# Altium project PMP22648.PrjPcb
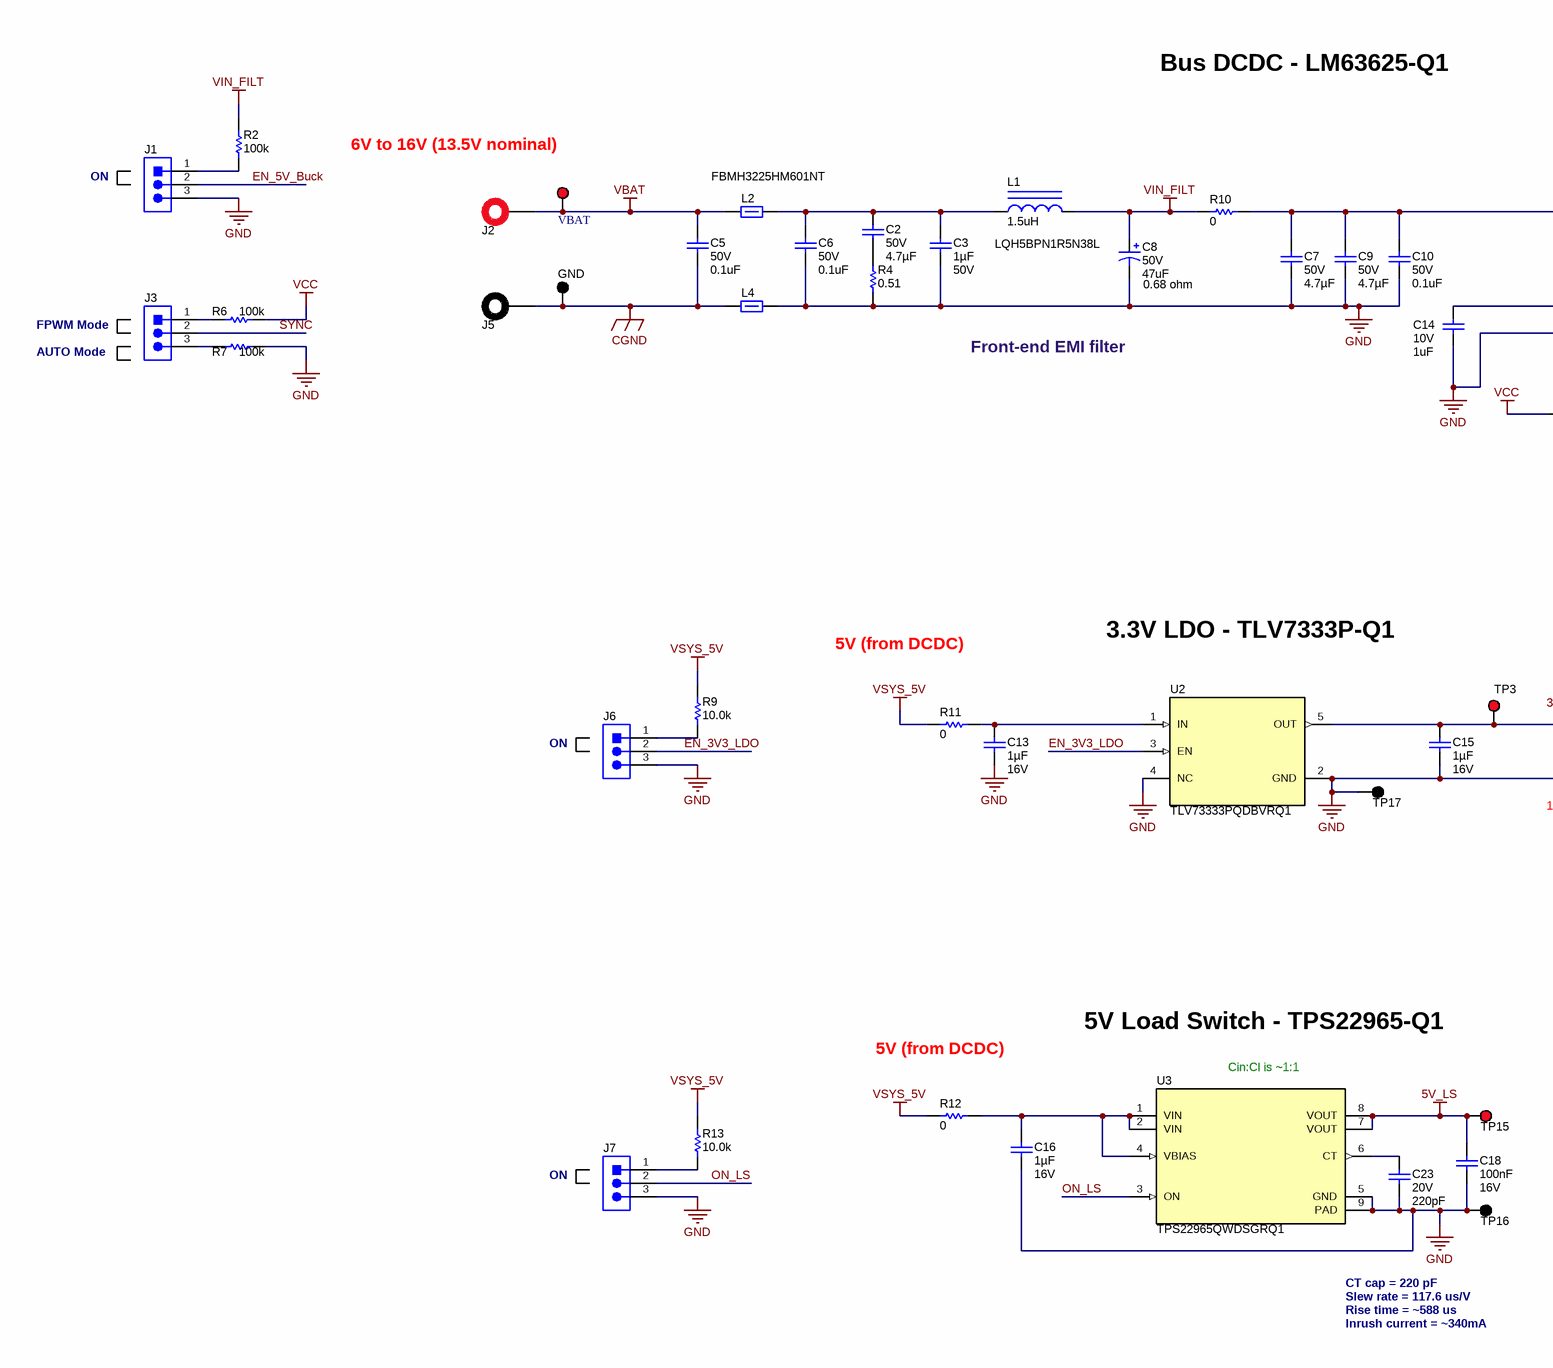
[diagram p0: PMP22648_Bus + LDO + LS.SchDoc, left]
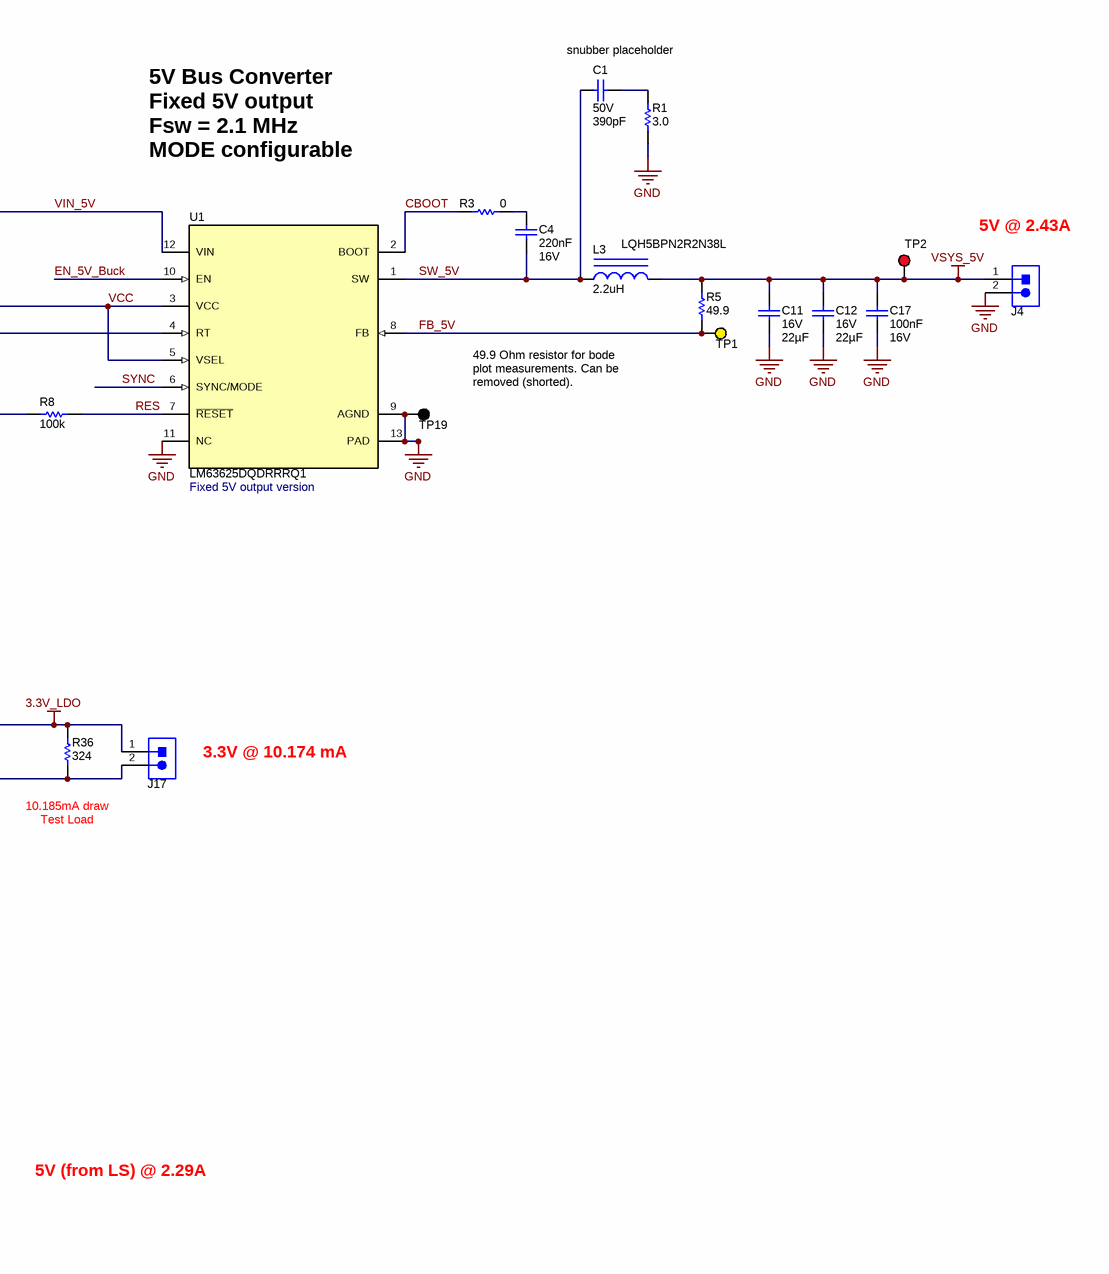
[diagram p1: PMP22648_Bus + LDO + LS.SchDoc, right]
CopyrightYear: 2020; PCB_Layout: Sahana Krishnan; PCB_Rev: E1; PRJ_Customer: Public Release; PRJ_Engineer: Sahana Krishnan; PRJ_Number: PMP22648; SCH_Rev: E1; TechSupport: http://www.ti.com/support; TID: N/A
2 sheets, 131 parts. Net scope: global (net labels, ports and power ports of the same name join across sheets).
Board file: PMP22648_PCB.PcbDoc
Sheets:
  PMP22648_Bus + LDO + LS.SchDoc
  PMP22648_PoL DCDC.SchDoc

## Sheet PMP22648_Bus + LDO + LS.SchDoc
size A2; Date: Not shown in title block; ApprovedBy: Not shown in title block; CheckedBy: Not shown in title block; Author: Not shown in title block; CompanyName: Not shown in title block; Engineer: Not shown in title block; Organization: Not shown in title block; Address1: Not shown in title block; Address2: Not shown in title block; Address3: Not shown in title block; Address4: Not shown in title block; DocumentNumber: 2; Revision: Use project parameter SCH_Rev; SheetNumber: 1; SheetTotal: 3; PageSetup: Record=PageOptions¦CenterHorizontal=True¦CenterVertical=True¦PrintScale=1.00¦XCorrection=1.00¦YCorrection=1.00¦PrintKind=0¦BorderSize=5000000¦LeftOffset=0¦BottomOffset=0¦Orientation=2¦PaperLength=1000¦PaperWidth=1000¦Scale=100¦PaperSource=15¦PrintQuality=600¦MediaType=1¦DitherType=10¦PaperKind=Letter¦PrintScaleMode=1

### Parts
C1  VDC_V: 50V  ValueDisplayed: 390pF  [0402S]  (hidden comment: GCM155R71H391KA37D)
C2  VDC_V: 50V  ValueDisplayed: 4.7µF  [1206_180]  (hidden comment: GCM31CC71H475KA03L)
C3  Cap_F: 1µF  VDC_V: 50V  [0805_HV]  (hidden comment: GCM21BR71H105KA03K)
C4  Cap_F: 220nF  VDC_V: 16V  [0603]  (hidden comment: GCM155R71C224KE02)
C5  VDC_V: 50V  ValueDisplayed: 0.1uF  [0402]  (hidden comment: GCM155R71H104KE02D)
C6  VDC_V: 50V  ValueDisplayed: 0.1uF  [0402]  (hidden comment: GCM155R71H104KE02D)
C7  VDC_V: 50V  ValueDisplayed: 4.7µF  [1206_180]  (hidden comment: GCM31CC71H475KA03L)
C8  Value1: 0.68 ohm  VDC_V: 50V  ValueDisplayed: 47uF  [Panasonic_D]  (hidden comment: EEEFT1H470AP)
C9  VDC_V: 50V  ValueDisplayed: 4.7µF  [1206_180]  (hidden comment: GCM31CC71H475KA03L)
C10  VDC_V: 50V  ValueDisplayed: 0.1uF  [0402]  (hidden comment: GCM155R71H104KE02D)
C11  VDC_V: 16V  ValueDisplayed: 22µF  [1210_270]  (hidden comment: CL32B226KOJVPNE)
C12  VDC_V: 16V  ValueDisplayed: 22µF  [1210_270]  (hidden comment: CL32B226KOJVPNE)
C13  Cap_F: 1µF  VDC_V: 16V  [0603]  (hidden comment: GCM188R71C105KA64J)
C14  VDC_V: 10V  ValueDisplayed: 1uF  [0402_070]  (hidden comment: GCM155C71A105KE38D)
C15  Cap_F: 1µF  VDC_V: 16V  [0603]  (hidden comment: GCM188R71C105KA64J)
C16  Cap_F: 1µF  VDC_V: 16V  [0603]  (hidden comment: GCM188R71C105KA64J)
C17  Cap_F: 100nF  VDC_V: 16V  [0603]  (hidden comment: GCM188R71C104KA37J)
C18  Cap_F: 100nF  VDC_V: 16V  [0603]  (hidden comment: GCM188R71C104KA37J)
C23  VDC_V: 20V  ValueDisplayed: 220pF  [0603]  (hidden comment: CGA3E2C0G1H221J080AA)
GND  5011  [Keystone5011]  (value not drawn)
J1  800-10-003-10-001000  [Mill-Max_800-10-003-10-001000]  (value not drawn)
J2  6091  [6091]  (value not drawn)
J3  800-10-003-10-001000  [Mill-Max_800-10-003-10-001000]  (value not drawn)
J4  PEC02SAAN  [CONN_PEC02SAAN]  (value not drawn)
J5  6092  [6092]  (value not drawn)
J6  800-10-003-10-001000  [Mill-Max_800-10-003-10-001000]  (value not drawn)
J7  800-10-003-10-001000  [Mill-Max_800-10-003-10-001000]  (value not drawn)
J17  PEC02SAAN  [CONN_PEC02SAAN]  (value not drawn)
L1  LQH5BPN1R5N38L  ValueDisplayed: 1.5uH  [LQH5BPN_38]
L2  FBMH3225HM601NT  [1210_280]
L3  LQH5BPN2R2N38L  ValueDisplayed: 2.2uH  [LQH5BPN_38]
L4  FBMH3225HM601NT  [1210_280]  (value not drawn)
R1  ValueDisplayed: 3.0  [0805]  (hidden comment: ERJ-6GEYJ3R0V)
R2  ValueDisplayed: 100k  [0402]  (hidden comment: RMCF0402FT100K)
R3  ValueDisplayed: 0  [0402S]  (hidden comment: CRCW04020000Z0EDHP)
R4  ValueDisplayed: 0.51  [0603]  (hidden comment: ERJ-3RQFR51V)
R5  ValueDisplayed: 49.9  [0402]  (hidden comment: ERJ-2RKF49R9X)
R6  ValueDisplayed: 100k  [0402]  (hidden comment: RMCF0402FT100K)
R7  ValueDisplayed: 100k  [0402]  (hidden comment: RMCF0402FT100K)
R8  ValueDisplayed: 100k  [0402]  (hidden comment: RMCF0402FT100K)
R9  ValueDisplayed: 10.0k  [0402]  (hidden comment: CRCW040210K0FKED)
R10  ValueDisplayed: 0  [1206]  (hidden comment: CRCW12060000Z0EAHP)
R11  ValueDisplayed: 0  [0402]  (hidden comment: CRCW04020000Z0EDHP)
R12  ValueDisplayed: 0  [1206]  (hidden comment: CRCW12060000Z0EAHP)
R13  ValueDisplayed: 10.0k  [0402]  (hidden comment: CRCW040210K0FKED)
R36  ValueDisplayed: 324  [0603]  (hidden comment: CRCW0603324RFKEA)
TP1  5014  [Keystone5014]  (value not drawn)
TP2  5010  [Keystone5010]  (value not drawn)
TP3  5010  [Keystone5010]  (value not drawn)
TP15  5010  [Keystone5010]  (value not drawn)
TP16  5011  [Keystone5011]  (value not drawn)
TP17  5011  [Keystone5011]  (value not drawn)
TP19  5011  [Keystone5011]  (value not drawn)
U1  LM63625DQDRRRQ1  [DRR0012E]
U2  TLV73333PQDBVRQ1  [DBV0005A_N]
U3  TPS22965QWDSGRQ1  [DSG0008B]
VBAT  5010  [Keystone5010]  (value not drawn)

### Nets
3.3V_LDO: C15.1 J17.1 R36.2 TP3.1 U2.5(OUT)
5V_LS: C18.1 TP15.1 U3.7(VOUT) U3.8(VOUT)
CGND: C5.2 GND.1 J5.1 L4.1
GND: C3.2 C6.2 C7.2 C8.2(-) C9.2 C10.2 C11.2 C12.2 C13.2 C14.2 C15.2 C16.2 C17.2 C18.2 C23.2 J1.3 J4.2 J6.3 J7.3 J17.2 L4.2 R1.1 R4.1 R7.1 R36.1 TP16.1 TP17.1 TP19.1 U1.4(RT) U1.9(AGND) U1.11(NC) U1.13(PAD) U2.2(GND) U2.4(NC) U3.5(GND) U3.9(PAD)
VBAT: C5.1 J2.1 L2.1 VBAT.1
VCC: C14.1 R6.1 R8.2 U1.3(VCC) U1.5(VSEL)
VIN_FILT: C8.1(+) L1.2 R2.2 R10.1
VSYS_5V: C11.1 C12.1 C17.1 J4.1 L3.2 R5.2 R9.1 R11.1 R12.1 R13.1 TP2.1
CBOOT: R3.2 U1.2(BOOT)
EN_3V3_LDO: J6.2 U2.3(EN)
EN_5V_Buck: J1.2 U1.10(EN)
FB_5V: R5.1 TP1.1 U1.8(FB)
ON_LS: J7.2 U3.3(ON)
RES: R8.1 U1.7(~{RESET})
SW_5V: C1.2 C4.2 L3.1 U1.1(SW)
SYNC: J3.2 U1.6(SYNC/MODE)
VIN_5V: C7.1 C9.1 C10.1 R10.2 U1.12(VIN)
NetC1_1: C1.1 R1.2
NetC2_1: C2.1 C3.1 C6.1 L1.1 L2.2
NetC2_2: C2.2 R4.2
NetC4_1: C4.1 R3.1
NetC13_1: C13.1 R11.2 U2.1(IN)
NetC16_1: C16.1 R12.2 U3.1(VIN) U3.2(VIN) U3.4(VBIAS)
NetC23_1: C23.1 U3.6(CT)
NetJ1_1: J1.1 R2.1
NetJ3_1: J3.1 R6.2
NetJ3_3: J3.3 R7.2
NetJ6_1: J6.1 R9.2
NetJ7_1: J7.1 R13.2

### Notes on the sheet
- Bus DCDC - LM63625-Q1
- snubber placeholder
- 6V to 16V (13.5V nominal)
- ON
- 5V Bus Converter
  Fixed 5V output
  Fsw = 2.1 MHz
  MODE configurable
- (near J4) 5V @ 2.43A
- FPWM Mode
- Front-end EMI filter
- AUTO Mode
- 49.9 Ohm resistor for bode plot measurements. Can be removed (shorted).
- (near U1) Fixed 5V output version
- 5V (from DCDC)
- 3.3V LDO - TLV7333P-Q1
- 3.3V @ 10.174 mA
- Test Load
- 10.185mA draw
- 5V Load Switch - TPS22965-Q1
- (near U3) Cin:Cl is
  :1
- 5V (from LS) @ 2.29A
- CT cap = 220 pF
- Slew rate = 117.6 us/V
- Rise time = ~588 us
- Inrush current = ~340mA

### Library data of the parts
C1 = CMP-0080703-2: CAP, CERM, 390 pF, 50 V,+/- 10%, X7R, AEC-Q200 Grade 1, 0402; Manufacturer: MuRata; Cap_Case: 0402; SizeX_mm: 1; SizeZ_mm: 0.6; SizeY_mm: 0.5; AEC Qualified: Y; Value: 390pF; Polarized: N; AEC Category: Q200; TaMax_C: 125°C; TaMin_C: -55°C; SizeAreaWB_mm2: 3; U/M: EA
C2 C7 C9 = CMP-0085643-1: CAP, CERM, 4.7 µF, 50 V,+/- 10%, X7S, AEC-Q200 Grade 1, 1206; Manufacturer: MuRata; SizeZ_mm: 1.8; Polarized: N; AEC Category: Q200; SizeY_mm: 1.6; SizeAreaWB_mm2: 10.92; SizeArea_mm2: 5.12; Value: 4.7uF; TaMin_C: -55°C; AEC Qualified: Y; SizeX_mm: 3.2; AEC Grade: 1; Cap_Case: 1206; U/M: EA; TaMax_C: 125°C
C3 = CMP-0086249-1: CAP, CERM, 1 µF, 50 V,+/- 10%, X7R, AEC-Q200 Grade 1, 0805; Manufacturer: MuRata; Value: 1uF; AEC Qualified: Y; AEC Category: Q200; U/M: EA; AEC Grade: 1; SizeArea_mm2: 2.5; SizeAreaWB_mm2: 6.75; SizeZ_mm: 1.45; SizeX_mm: 2; Cap_Case: 0805; TaMax_C: 125°C; Polarized: N; SizeY_mm: 1.25; TaMin_C: -55°C
C4 = CMP-0007125-4: CAP, CERM, 0.22 uF, 16 V, +/- 10%, X7R, AEC-Q200 Grade 1, 0603; Manufacturer: MuRata; TaMin_C: -55°C; Polarized: N; SizeAreaWB_mm2: 4.68; Value1: Unknown; U/M: EA; Value: 0.22uF; TaMax_C: 125°C; SizeZ_mm: 1; SizeX_mm: 1.6; SizeY_mm: 0.8; SizeArea_mm2: 1.28; AEC Qualified: Y; AEC Category: Q200
C5 C6 C10 = CMP-0006356-1: CAP, CERM, 0.1 uF, 50 V, +/- 10%, X7R, AEC-Q200 Grade 1, 0402; Manufacturer: MuRata; TaMin_C: -55°C; Polarized: N; SizeAreaWB_mm2: 3; Value1: Unknown; U/M: EA; Value: 0.1uF; TaMax_C: 125°C; SizeZ_mm: 0.6; SizeX_mm: 1; SizeY_mm: 0.5; AEC Qualified: Y; Cap_F: 100nF; AEC Category: Q200
C8 = CMP-0011204-2: CAP, AL, 47 uF, 50 V, +/- 20%, 0.68 ohm, AEC-Q200 Grade 2, SMD; Manufacturer: Panasonic; TaMin_C: -55°C; ESR_ohm: 0.68; Polarized: Y; SizeAreaWB_mm2: 73.96; U/M: EA; Value: 47uF; TaMax_C: 105°C; SizeZ_mm: 6.1; SizeX_mm: 6.6; Cap_Case: 6.3x5.8mm; SizeArea_mm2: 43.56; CompType: Capacitor; Cap_F: 47µF; IRMS_A: 195mA; AEC Grade: 2; AEC Category: Q200
C11 C12 = CMP-0083755-1: CAP, CERM, 22 µF, 16 V,+/- 10%, X7R, AEC-Q200 Grade 1, 1210; Manufacturer: Samsung Electro-Mechanics; SizeAreaWB_mm2: 14.7; SizeArea_mm2: 8; AEC Qualified: Y; AEC Category: Q200; Value: 22uF; TaMax_C: 125°C; SizeZ_mm: 2.7; AEC Grade: 1; Polarized: N; TaMin_C: -55°C; SizeY_mm: 2.5; U/M: EA; SizeX_mm: 3.2; Cap_Case: 1210
C13 C15 C16 = CMP-0079154-1: CAP, CERM, 1 µF, 16 V,+/- 10%, X7R, AEC-Q200 Grade 1, 0603; Manufacturer: MuRata; SizeAreaWB_mm2: 4.68; SizeArea_mm2: 1.28; AEC Qualified: Y; AEC Category: Q200; Value: 1uF; TaMax_C: 125°C; SizeZ_mm: 1; Polarized: N; TaMin_C: -55°C; SizeY_mm: 0.8; U/M: EA; SizeX_mm: 1.6
C14 = CMP-0006349-2: CAP, CERM, 1 uF, 10 V, +/- 10%, X7S, AEC-Q200 Grade 1, 0402; Manufacturer: MuRata; TaMin_C: -55°C; Polarized: N; SizeAreaWB_mm2: 3; Value1: Unknown; U/M: EA; Value: 1uF; TaMax_C: 125°C; SizeZ_mm: 0.7; SizeX_mm: 1; SizeY_mm: 0.5; Cap_Case: 0402; AEC Qualified: Y; Cap_F: 1µF; AEC Category: Q200
C17 C18 = CMP-0007135-2: CAP, CERM, 0.1 uF, 16 V, +/- 10%, X7R, AEC-Q200 Grade 1, 0603; Manufacturer: MuRata; TaMin_C: -55°C; Polarized: N; SizeAreaWB_mm2: 4.68; Value1: Unknown; U/M: EA; Value: 0.1uF; TaMax_C: 125°C; SizeZ_mm: 1; SizeX_mm: 1.6; SizeY_mm: 0.8; SizeArea_mm2: 1.28; AEC Qualified: Y; AEC Category: Q200
C23 = CMP-0007072-2: CAP, CERM, 220 pF, 20 V, +/- 5%, C0G/NP0, AEC-Q200 Grade 1, 0603; Manufacturer: TDK; TaMin_C: -55°C; Polarized: N; SizeAreaWB_mm2: 4.68; Value1: Unknown; U/M: EA; Value: 220pF; TaMax_C: 125°C; SizeZ_mm: 1; SizeX_mm: 1.6; SizeY_mm: 0.8; SizeArea_mm2: 1.28; AEC Qualified: Y; AEC Category: Q200
GND TP16 TP17 TP19 = CMP-0055148-1: Test Point, Multipurpose, Black, TH; Manufacturer: Keystone; CNHeader: FALSE; Green_Lifecycle: Active; Green_REACh: Passed; ContactFinish: Silver; CT: TRUE
J1 J3 J6 J7 = CMP-0055086-1: Header, 100mil, 3x1, TH; Manufacturer: Mill-Max; CNHeader: TRUE; Green_Lifecycle: Active; Green_REACh: Passed; CT: FALSE
J2 = CMP-0055167-2: Standard Banana Jack, Insulated, Red; Manufacturer: Keystone; CT: TRUE; Green_REACh: Passed; CNHeader: FALSE; Green_Lifecycle: Active
J4 J17 = CMP-0002337-1: Header, 100mil, 2x1, Tin, TH; Manufacturer: Sullins Connector Solutions; CNHeader: TRUE; Current_A: 3A; Green_Lifecycle: Not Set; Shrouded: N; Gender: Male; Green_REACh: Incomplete; Voltage_V: 1.8kV; Row_Count: 1; Pitch_mm: 2.54; CT: FALSE; Cert_UL: Y
J5 = CMP-0055168-2: Standard Banana Jack, Insulated, Black; Manufacturer: Keystone; CT: TRUE; Green_REACh: Passed; CNHeader: FALSE; Green_Lifecycle: Active
L1 = CMP-0058725-1: Inductor, Wirewound, Ferrite, 1.5 uH, 4.5 A, 0.0168 ohm, SMD; Manufacturer: MuRata; Isat: 6.5A @ 30% inductance drop; Irms: 4.5A @ 40C rise; SizeAreaWB_mm2: 34.81; DCR_ohm: 0.0168; Value: 1.5uH; Imax_A: 4.5A; SizeZ_mm: 4; SizeX_mm: 4.9; SizeArea_mm2: 24.01; Ind_H: 1.5µH; AEC Qualified: N; AEC Category: Q200
L2 L4 = CMP-0003374-1: Ferrite Bead, 600 ohm @ 100 MHz, 3 A, 1210; Manufacturer: Taiyo Yuden; ZTyp@100MHz_Ohm: 600; SizeAreaWB_mm2: 14.7; DCR_ohm: 0.042; Value1: 0.042 ohm; Value: 600 ohm; Imax_A: 3A; SizeZ_mm: 2.8; SizeX_mm: 3.2; SizeY_mm: 2.5; SizeArea_mm2: 8
L3 = CMP-0058726-1: Inductor, Wirewound, Ferrite, 2.2 uH, 4.3 A, 0.0192 ohm, SMD; Manufacturer: MuRata; Isat: 5A @ 30% inductance drop; Irms: 4.3A @ 40C rise; SizeAreaWB_mm2: 34.81; DCR_ohm: 0.0192; Value: 2.2uH; Imax_A: 4.3A; SizeZ_mm: 4; SizeX_mm: 4.9; SizeArea_mm2: 24.01; Ind_H: 2.2µH; AEC Qualified: N; AEC Category: Q200
R1 = CMP-0020720-3: RES, 3.0, 5%, 0.125 W, AEC-Q200 Grade 0, 0805; Manufacturer: Panasonic; Power_W: 125mW; TempCo: 600 ppm/C; Value_Code: 3R00; Value: 3.0; EIA_Code: E24; Res_ohm: 3; SizeX_mm: 2; SizeY_mm: 1.25; SizeZ_mm: 1.45; Value2: 0.125W; SizeArea_mm2: 2.5; AEC Qualified: Y; VDC_V: 150V; AEC Category: Q200; AEC Grade: 0; SizeAreaWB_mm2: 6.75
R2 R6-R8 = CMP-0026753-1: RES, 100 k, 1%, 0.063 W, AEC-Q200 Grade 0, 0402; Manufacturer: Stackpole Electronics Inc; Power_W: 63mW; TempCo: 100 ppm/C; U/M: EA; Value: 100k; EIA_Code: E96; SizeX_mm: 1; SizeY_mm: 0.5; SizeZ_mm: 0.6; Value2: 0.063W; AEC Qualified: Y; VDC_V: 50V; AEC Grade: 0; AEC Category: Q200
R3 R11 = CMP-0081856-1: RES, 0, 0%, 0.2 W, AEC-Q200 Grade 0, 0402; Manufacturer: Vishay-Dale; SizeAreaWB_mm2: 3; SizeArea_mm2: 0.5; AEC Qualified: Y; AEC Category: Q200; Value: 0; SizeZ_mm: 0.6; Power_W: 200mW; VDC_V: 50V; Value2: 0.2W; SizeX_mm: 1
R4 = CMP-0022717-2: RES, 0.51, 1%, 0.1 W, AEC-Q200 Grade 1, 0603; Manufacturer: Panasonic; Power_W: 100mW; TempCo: 300 ppm/C; Value_Code: R510; U/M: EA; Value: 0.51; EIA_Code: E96; SizeX_mm: 1.6; SizeY_mm: 0.8; SizeZ_mm: 1; Value2: 0.1W; SizeArea_mm2: 1.28; AEC Qualified: Y; AEC Category: Q200
R5 = CMP-0026703-1: RES, 49.9, 1%, 0.1 W, AEC-Q200 Grade 0, 0402; Manufacturer: Panasonic; Power_W: 100mW; TempCo: 100 ppm/C; Value_Code: 49R9; U/M: EA; Value: 49.9; EIA_Code: E96; SizeX_mm: 1; SizeY_mm: 0.5; SizeZ_mm: 0.6; Value2: 0.1W; AEC Qualified: Y; VDC_V: 50V; AEC Grade: 0; AEC Category: Q200
R9 R13 = CMP-0025958-3: RES, 10.0 k, 1%, 0.063 W, AEC-Q200 Grade 0, 0402; Manufacturer: Vishay-Dale; Power_W: 63mW; TempCo: 100 ppm/C; Value_Code: 10k0; Value: 10.0k; EIA_Code: E96; Res_ohm: 10k; SizeX_mm: 1; SizeY_mm: 0.5; SizeZ_mm: 0.6; Value2: 0.063W; AEC Qualified: Y; VDC_V: 50V; AEC Category: Q200; AEC Grade: 0
R10 R12 = CMP-0086176-1: RES, 0, 0.75 W, AEC-Q200 Grade 0, 1206; Manufacturer: Vishay-Dale; Value: 0; SizeY_mm: 1.6; SizeX_mm: 3.2; Tolerance_%: 0%; SizeArea_mm2: 5.12; EIA_Code: E96; SizeAreaWB_mm2: 10.92; Power_W: 750mW; AEC Qualified: Y; SizeZ_mm: 1.35; Value2: 0.75W; AEC Category: Q200; VDC_V: 200V
R36 = CMP-0022333-5: RES, 324, 1%, 0.1 W, AEC-Q200 Grade 0, 0603; Manufacturer: Vishay-Dale; Power_W: 100mW; TempCo: 100 ppm/C; Value_Code: 324R; Value: 324; EIA_Code: E96; SizeX_mm: 1.6; SizeY_mm: 0.8; SizeZ_mm: 1; Value2: 0.1W; SizeArea_mm2: 1.28; AEC Qualified: Y; VDC_V: 75V; AEC Category: Q200; AEC Grade: 0
TP1 = CMP-0055151-1: Test Point, Multipurpose, Yellow, TH; Manufacturer: Keystone; CNHeader: FALSE; Green_Lifecycle: Active; Green_REACh: Passed; ContactFinish: Silver; CT: TRUE
TP2 TP3 TP15 VBAT = CMP-0055147-1: Test Point, Multipurpose, Red, TH; Manufacturer: Keystone; CNHeader: FALSE; Green_Lifecycle: Active; Green_REACh: Passed; ContactFinish: Silver; CT: TRUE
U1 = CMP-0861031-1: 3.5-V to 36-V, 2.5-A, Automotive Step-down Voltage Converter, DRR0012E (WSON-12); Manufacturer: Texas Instruments; AEC Category: Q200; SizeArea_mm2: 9; SizeAreaWB_mm2: 16; CompType: IC; AEC Qualified: Y; SizeY_mm: 3; SizeZ_mm: 0.8
U2 = CMP-0860155-1: Automotive capacitor-free 300-mA LDO regulator with foldback current limit for portable devices, DBV0005A (SOT-23-5); Manufacturer: Texas Instruments; SizeAreaWB_mm2: 14.82; SizeArea_mm2: 8.12; SizeY_mm: 2.9; CompType: IC; SizeZ_mm: 1.45; SizeX_mm: 2.8; AEC Category: Q200; AEC Qualified: Y
U3 = CMP-0073677-2: 5.5V, 4A, 16mΩ Automotive Load Switch With Adjustable Rise Time and Optional Quick Output Discharge, DSG0008B (WSON-8); Alternate Manufacturer: Texas Instruments; Green_Lifecycle: Active; SizeAreaWB_mm2: 9.0; Green_REACh: Passed; U/M: EA; SizeZ_mm: 0.8; SizeX_mm: 2.0; SizeArea_mm2: 4.0; CompType: IC

## Sheet PMP22648_PoL DCDC.SchDoc
size A2; Date: Not shown in title block; ApprovedBy: Not shown in title block; CheckedBy: Not shown in title block; Author: Not shown in title block; CompanyName: Not shown in title block; Engineer: Not shown in title block; Organization: Not shown in title block; Address1: Not shown in title block; Address2: Not shown in title block; Address3: Not shown in title block; Address4: Not shown in title block; DocumentNumber: 2; Revision: Use project parameter SCH_Rev; SheetNumber: 2; SheetTotal: 3; PageSetup: Record=PageOptions¦CenterHorizontal=True¦CenterVertical=True¦PrintScale=1.00¦XCorrection=1.00¦YCorrection=1.00¦PrintKind=0¦BorderSize=5000000¦LeftOffset=0¦BottomOffset=0¦Orientation=2¦PaperLength=1000¦PaperWidth=1000¦Scale=100¦PaperSource=15¦PrintQuality=600¦MediaType=1¦DitherType=10¦PaperKind=Letter¦PrintScaleMode=1
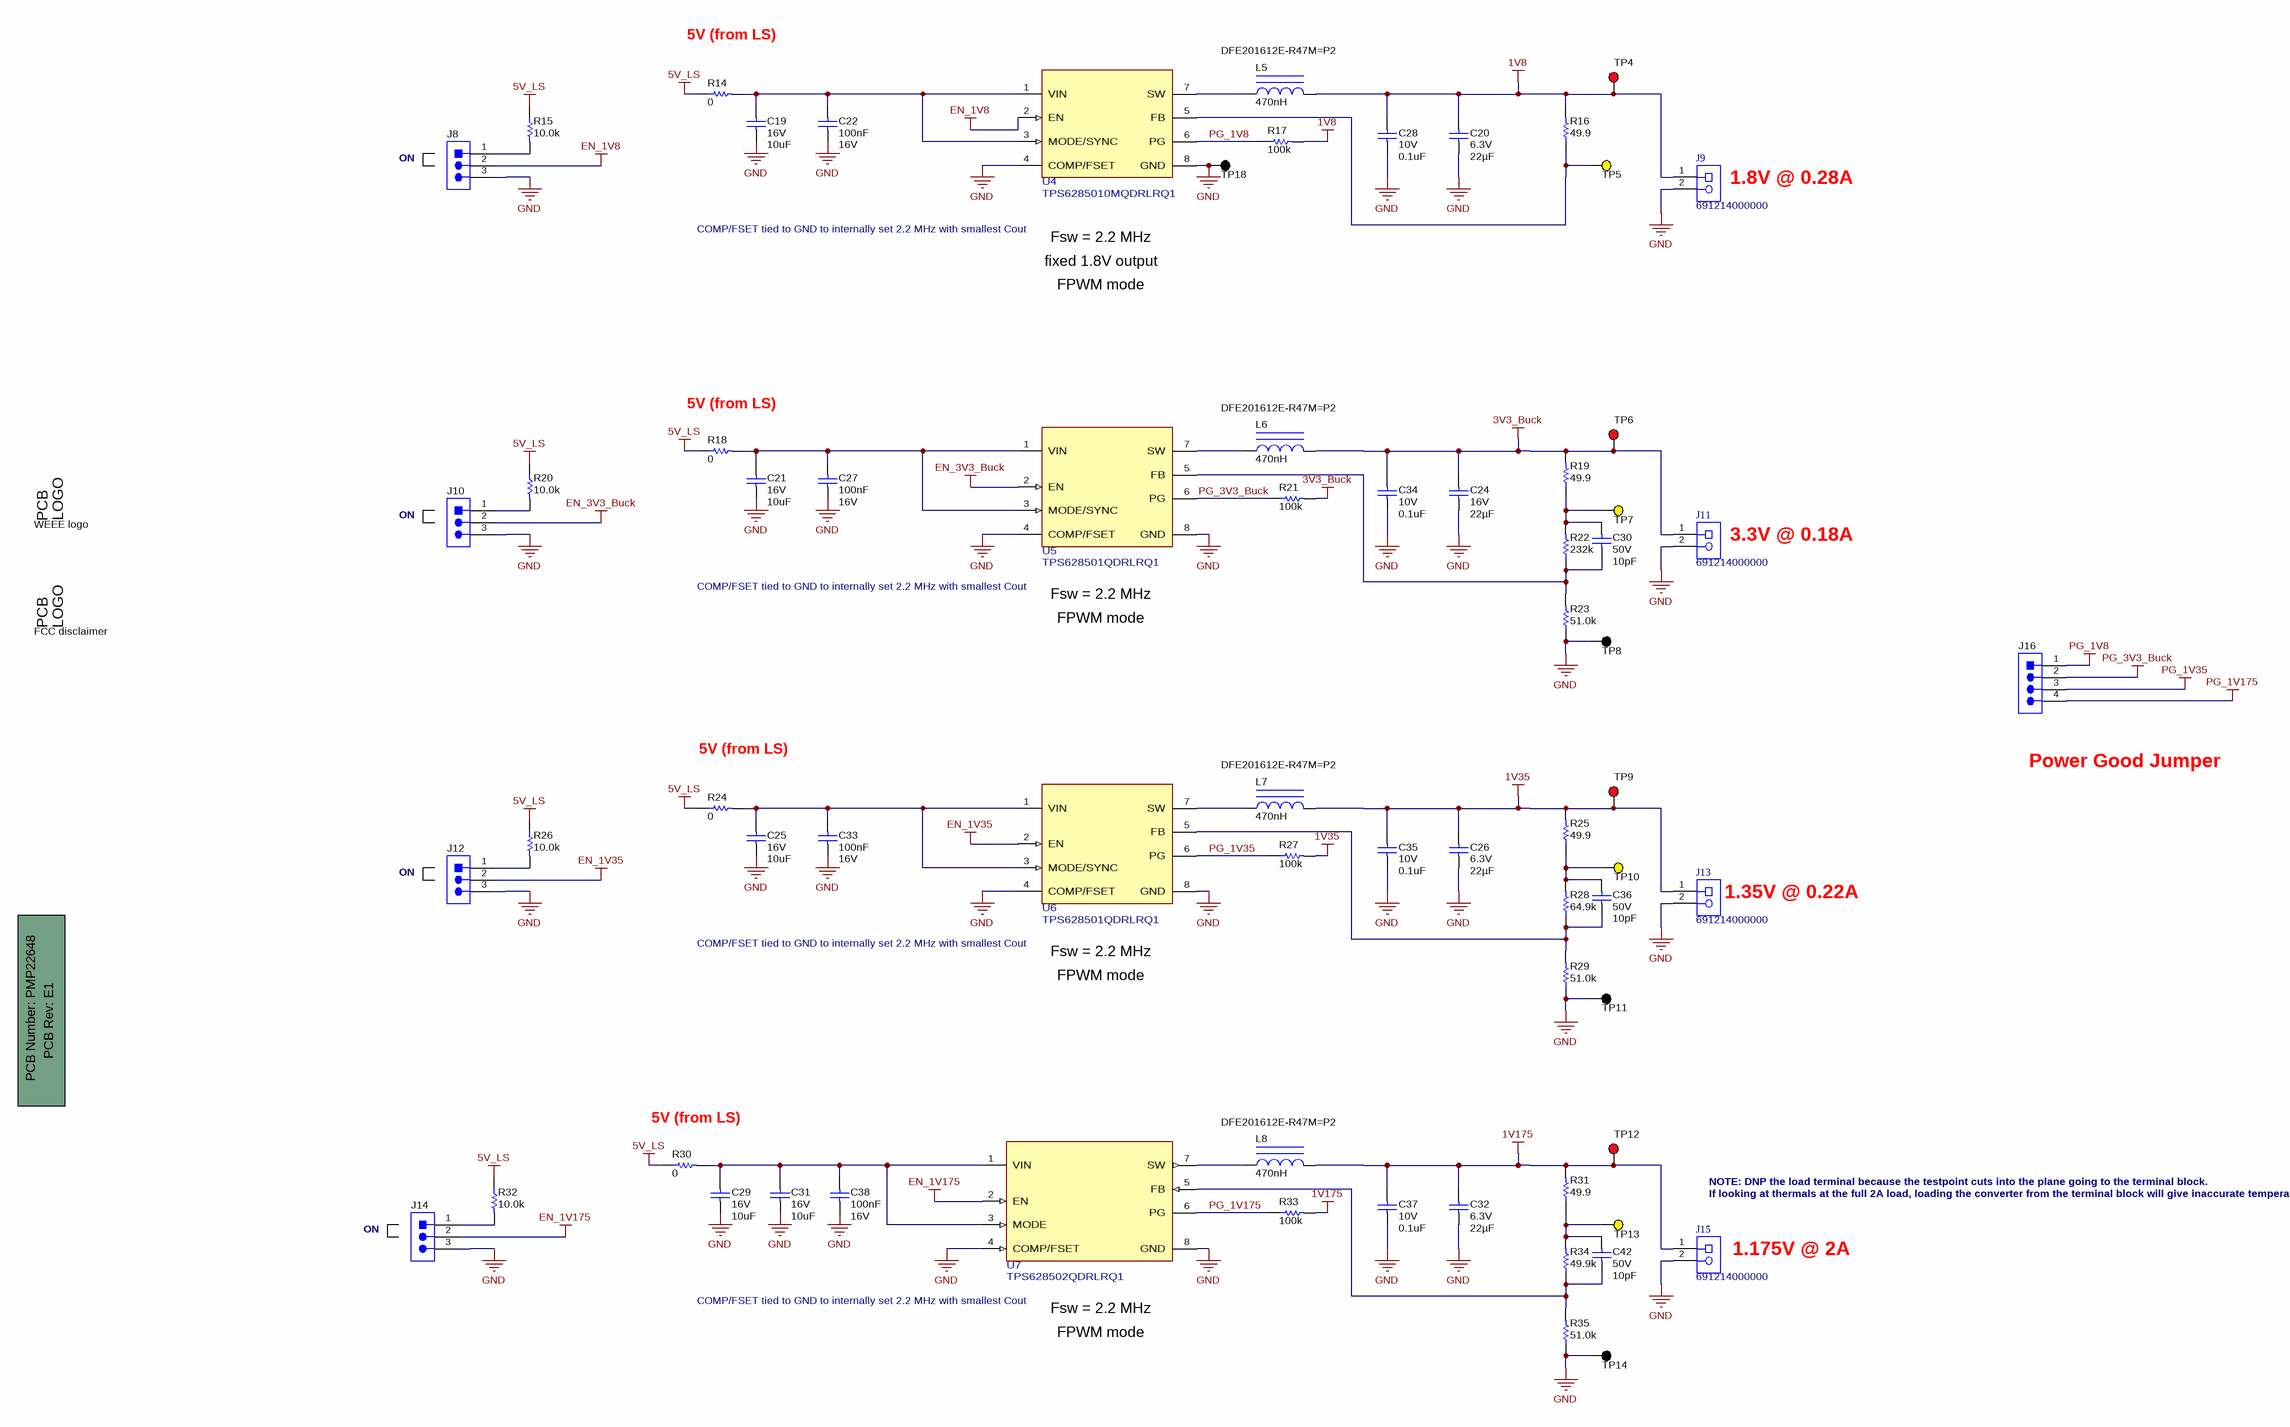
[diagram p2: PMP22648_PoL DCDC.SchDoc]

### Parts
!PCB1  Printed Circuit Board  (value not drawn)  (mechanical)
C19  VDC_V: 16V  ValueDisplayed: 10uF  [0805_HV]  (hidden comment: CGA4J1X7S1C106K125AC)
C20  VDC_V: 6.3V  ValueDisplayed: 22µF  [1206_180]  (hidden comment: GCM31CR70J226ME23L)
C21  VDC_V: 16V  ValueDisplayed: 10uF  [0805_HV]  (hidden comment: CGA4J1X7S1C106K125AC)
C22  Cap_F: 100nF  VDC_V: 16V  [0603]  (hidden comment: GCM188R71C104KA37J)
C24  VDC_V: 16V  ValueDisplayed: 22µF  [1210_270]  (hidden comment: CL32B226KOJVPNE)
C25  VDC_V: 16V  ValueDisplayed: 10uF  [0805_HV]  (hidden comment: CGA4J1X7S1C106K125AC)
C26  VDC_V: 6.3V  ValueDisplayed: 22µF  [1206_180]  (hidden comment: GCM31CR70J226ME23L)
C27  Cap_F: 100nF  VDC_V: 16V  [0603]  (hidden comment: GCM188R71C104KA37J)
C28  VDC_V: 10V  ValueDisplayed: 0.1uF  [0402]  (hidden comment: GCM155R71A104KA55D)
C29  VDC_V: 16V  ValueDisplayed: 10uF  [0805_HV]  (hidden comment: CGA4J1X7S1C106K125AC)
C30  VDC_V: 50V  ValueDisplayed: 10pF  [0402]  (hidden comment: GCM1555C1H100JA16D)
C31  VDC_V: 16V  ValueDisplayed: 10uF  [0805_HV]  (hidden comment: CGA4J1X7S1C106K125AC)
C32  VDC_V: 6.3V  ValueDisplayed: 22µF  [1206_180]  (hidden comment: GCM31CR70J226ME23L)
C33  Cap_F: 100nF  VDC_V: 16V  [0603]  (hidden comment: GCM188R71C104KA37J)
C34  VDC_V: 10V  ValueDisplayed: 0.1uF  [0402]  (hidden comment: GCM155R71A104KA55D)
C35  VDC_V: 10V  ValueDisplayed: 0.1uF  [0402]  (hidden comment: GCM155R71A104KA55D)
C36  VDC_V: 50V  ValueDisplayed: 10pF  [0402]  (hidden comment: GCM1555C1H100JA16D)
C37  VDC_V: 10V  ValueDisplayed: 0.1uF  [0402]  (hidden comment: GCM155R71A104KA55D)
C38  Cap_F: 100nF  VDC_V: 16V  [0603]  (hidden comment: GCM188R71C104KA37J)
C42  VDC_V: 50V  ValueDisplayed: 10pF  [0402]  (hidden comment: GCM1555C1H100JA16D)
J8  800-10-003-10-001000  [Mill-Max_800-10-003-10-001000]  (value not drawn)
J9  691214000000  [Wurth_691214110002]
J10  800-10-003-10-001000  [Mill-Max_800-10-003-10-001000]  (value not drawn)
J11  691214000000  [Wurth_691214110002]
J12  800-10-003-10-001000  [Mill-Max_800-10-003-10-001000]  (value not drawn)
J13  691214000000  [Wurth_691214110002]
J14  800-10-003-10-001000  [Mill-Max_800-10-003-10-001000]  (value not drawn)
J15  691214000000  [Wurth_691214110002]
J16  800-10-004-10-001000  [Mill-Max_800-10-004-10-001000]  (value not drawn)
L5  DFE201612E-R47M=P2  ValueDisplayed: 470nH  [DFE201612E]
L6  DFE201612E-R47M=P2  ValueDisplayed: 470nH  [DFE201612E]
L7  DFE201612E-R47M=P2  ValueDisplayed: 470nH  [DFE201612E]
L8  DFE201612E-R47M=P2  ValueDisplayed: 470nH  [DFE201612E]
Logo1  WEEE logo  [WEEE_Minimum]  (no BOM)
Logo2  FCC disclaimer  [FCC_disclaimer]  (no BOM)
R14  ValueDisplayed: 0  [0402]  (hidden comment: CRCW04020000Z0EDHP)
R15  ValueDisplayed: 10.0k  [0402]  (hidden comment: CRCW040210K0FKED)
R16  ValueDisplayed: 49.9  [0402]  (hidden comment: ERJ-2RKF49R9X)
R17  ValueDisplayed: 100k  [0402]  (hidden comment: RMCF0402FT100K)
R18  ValueDisplayed: 0  [0402]  (hidden comment: CRCW04020000Z0EDHP)
R19  ValueDisplayed: 49.9  [0402]  (hidden comment: ERJ-2RKF49R9X)
R20  ValueDisplayed: 10.0k  [0402]  (hidden comment: CRCW040210K0FKED)
R21  ValueDisplayed: 100k  [0402]  (hidden comment: RMCF0402FT100K)
R22  ValueDisplayed: 232k  [0402]  (hidden comment: CRCW0402232KFKED)
R23  ValueDisplayed: 51.0k  [0402]  (hidden comment: ERJ-2RKF5102X)
R24  ValueDisplayed: 0  [0402]  (hidden comment: CRCW04020000Z0EDHP)
R25  ValueDisplayed: 49.9  [0402]  (hidden comment: ERJ-2RKF49R9X)
R26  ValueDisplayed: 10.0k  [0402]  (hidden comment: CRCW040210K0FKED)
R27  ValueDisplayed: 100k  [0402]  (hidden comment: RMCF0402FT100K)
R28  ValueDisplayed: 64.9k  [0402]  (hidden comment: CRCW040264K9FKED)
R29  ValueDisplayed: 51.0k  [0402]  (hidden comment: ERJ-2RKF5102X)
R30  ValueDisplayed: 0  [0805_HV]  (hidden comment: PMR10EZPJ000)
R31  ValueDisplayed: 49.9  [0402]  (hidden comment: ERJ-2RKF49R9X)
R32  ValueDisplayed: 10.0k  [0402]  (hidden comment: CRCW040210K0FKED)
R33  ValueDisplayed: 100k  [0402]  (hidden comment: RMCF0402FT100K)
R34  ValueDisplayed: 49.9k  [0402]  (hidden comment: ERJ-2RKF4992X)
R35  ValueDisplayed: 51.0k  [0402]  (hidden comment: ERJ-2RKF5102X)
TP4  5010  [Keystone5010]  (value not drawn)
TP5  5014  [Keystone5014]  (value not drawn)
TP6  5010  [Keystone5010]  (value not drawn)
TP7  5014  [Keystone5014]  (value not drawn)
TP8  5011  [Keystone5011]  (value not drawn)
TP9  5010  [Keystone5010]  (value not drawn)
TP10  5014  [Keystone5014]  (value not drawn)
TP11  5011  [Keystone5011]  (value not drawn)
TP12  5010  [Keystone5010]  (value not drawn)
TP13  5014  [Keystone5014]  (value not drawn)
TP14  5011  [Keystone5011]  (value not drawn)
TP18  5011  [Keystone5011]  (value not drawn)
U4  TPS6285010MQDRLRQ1  [DRL0008A-MFG]
U5  TPS628501QDRLRQ1  [DRL0008A-MFG]
U6  TPS628501QDRLRQ1  [DRL0008A-MFG]
U7  TPS628502QDRLRQ1  [DRL0008A-MFG]

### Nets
1V8: C20.1 C28.1 J9.1 L5.2 R16.2 R17.2 TP4.1
1V35: C26.1 C35.1 J13.1 L7.2 R25.2 R27.2 TP9.1
1V175: C32.1 C37.1 J15.1 L8.2 R31.2 R33.2 TP12.1
3V3_Buck: C24.1 C34.1 J11.1 L6.2 R19.2 R21.2 TP6.1
5V_LS: R14.1 R15.1 R18.1 R20.1 R24.1 R26.1 R30.1 R32.1
EN_1V8: J8.2 U4.2(EN)
EN_1V35: J12.2 U6.2(EN)
EN_1V175: J14.2 U7.2(EN)
EN_3V3_Buck: J10.2 U5.2(EN)
GND: C19.2 C20.2 C21.2 C22.2 C24.2 C25.2 C26.2 C27.2 C28.2 C29.2 C31.2 C32.2 C33.2 C34.2 C35.2 C37.2 C38.2 J8.3 J9.2 J10.3 J11.2 J12.3 J13.2 J14.3 J15.2 R23.1 R29.1 R35.1 TP8.1 TP11.1 TP14.1 TP18.1 U4.4(COMP/FSET) U4.8(GND) U5.4(COMP/FSET) U5.8(GND) U6.4(COMP/FSET) U6.8(GND) U7.4(COMP/FSET) U7.8(GND)
PG_1V8: J16.1 R17.1 U4.6(PG)
PG_1V35: J16.3 R27.1 U6.6(PG)
PG_1V175: J16.4 R33.1 U7.6(PG)
PG_3V3_Buck: J16.2 R21.1 U5.6(PG)
NetC19_1: C19.1 C22.1 R14.2 U4.1(VIN) U4.3(MODE/SYNC)
NetC21_1: C21.1 C27.1 R18.2 U5.1(VIN) U5.3(MODE/SYNC)
NetC25_1: C25.1 C33.1 R24.2 U6.1(VIN) U6.3(MODE/SYNC)
NetC29_1: C29.1 C31.1 C38.1 R30.2 U7.1(VIN) U7.3(MODE)
NetC30_1: C30.1 R19.1 R22.2 TP7.1
NetC30_2: C30.2 R22.1 R23.2 U5.5(FB)
NetC36_1: C36.1 R25.1 R28.2 TP10.1
NetC36_2: C36.2 R28.1 R29.2 U6.5(FB)
NetC42_1: C42.1 R31.1 R34.2 TP13.1
NetC42_2: C42.2 R34.1 R35.2 U7.5(FB)
NetJ8_1: J8.1 R15.2
NetJ10_1: J10.1 R20.2
NetJ12_1: J12.1 R26.2
NetJ14_1: J14.1 R32.2
NetL5_1: L5.1 U4.7(SW)
NetL6_1: L6.1 U5.7(SW)
NetL7_1: L7.1 U6.7(SW)
NetL8_1: L8.1 U7.7(SW)
NetR16_1: R16.1 TP5.1 U4.5(FB)

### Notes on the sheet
- 5V (from LS)
- ON
- (near J9) 1.8V @ 0.28A
- COMP/FSET tied to GND to internally set 2.2 MHz with smallest Cout
- Fsw = 2.2 MHz
- fixed 1.8V output
- FPWM mode
- (near R18) 5V (from LS)
- (near J11) 3.3V @ 0.18A
- Power Good Jumper
- (near J13) 1.35V @ 0.22A
- (near R30) 5V (from LS)
- NOTE: DNP the load terminal because the testpoint cuts into the plane going to the terminal block.
- If looking at thermals at the full 2A load, loading the converter from the terminal block will give inaccurate temperature rise.
- (near J15) 1.175V @ 2A

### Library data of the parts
!PCB1 = CMP-0003618-2: Manufacturer: Any; PartNumber: PMP22648
C19 C21 C25 C29 C31 = CMP-0007965-1: CAP, CERM, 10 uF, 16 V, +/- 10%, X7S, AEC-Q200 Grade 1, 0805; Manufacturer: TDK; TaMin_C: -55°C; Polarized: N; SizeAreaWB_mm2: 6.75; Value1: Unknown; U/M: EA; Value: 10uF; TaMax_C: 125°C; SizeZ_mm: 1.45; SizeX_mm: 2; SizeY_mm: 1.25; Cap_Case: 0805; SizeArea_mm2: 2.5; AEC Qualified: Y; Cap_F: 10µF; AEC Grade: 1; AEC Category: Q200
C20 C26 C32 = CMP-0085979-1: CAP, CERM, 22 µF, 6.3 V,+/- 20%, X7R, AEC-Q200 Grade 1, 1206; Manufacturer: MuRata; U/M: EA; SizeAreaWB_mm2: 10.92; Polarized: N; SizeX_mm: 3.2; Value: 22uF; AEC Qualified: Y; SizeY_mm: 1.6; SizeArea_mm2: 5.12; TaMax_C: 125°C; SizeZ_mm: 1.8; AEC Category: Q200; Cap_Case: 1206; TaMin_C: -55°C; AEC Grade: 1
C22 C27 C33 C38 = CMP-0007135-2: as C17 on sheet PMP22648_Bus + LDO + LS
C24 = CMP-0083755-1: as C11 on sheet PMP22648_Bus + LDO + LS
C28 C34 C35 C37 = CMP-0006350-2: CAP, CERM, 0.1 uF, 10 V, +/- 10%, X7R, AEC-Q200 Grade 1, 0402; Manufacturer: MuRata; TaMin_C: -55°C; Polarized: N; SizeAreaWB_mm2: 3; Value1: Unknown; U/M: EA; Value: 0.1uF; TaMax_C: 125°C; SizeZ_mm: 0.6; SizeX_mm: 1; SizeY_mm: 0.5; AEC Qualified: Y; Cap_F: 100nF; AEC Category: Q200
C30 C36 C42 = CMP-0860290-1: CAP, CERM, 10 pF, 50 V,+/- 5%, C0G/NP0, AEC-Q200 Grade 1, 0402; Manufacturer: MuRata; TaMin_C: -55°C; AEC Grade: 1; AEC Qualified: Y; SizeAreaWB_mm2: 3; SizeZ_mm: 0.6; Value: 10pF; TaMax_C: 125°C; Polarized: N; SizeArea_mm2: 0.5; U/M: EA; AEC Category: Q200
J8 J10 J12 J14 = CMP-0055086-1: as J1 on sheet PMP22648_Bus + LDO + LS
J9 J11 J13 J15 = CMP-0054825-1: Terminal Block, 3.5mm, 2x1, Tin, TH; Manufacturer: Wurth Elektronik; CNHeader: FALSE; Current_A: 10A; Gender: Female; Voltage_V: 300V; Row_Count: 1; Pitch_mm: 3.5; CT: TRUE; Cert_UL: Y
J16 = CMP-0055087-1: Header, 100mil, 4x1, TH; Manufacturer: Mill-Max; CT: FALSE; CNHeader: TRUE
L5-L8 = CMP-0080779-1: Inductor, Shielded, Metal Composite, 470 nH, 4.5 A, 0.026 ohm, SMD; Manufacturer: MuRata; Isat: 5.5A @ 30% inductance drop; Irms: 4.5A @ 40C rise; SizeAreaWB_mm2: 7.8; DCR_ohm: 0.026; Value: 470nH; Imax_A: 4.5A; SizeZ_mm: 1.2; SizeX_mm: 2; SizeY_mm: 1.6; SizeArea_mm2: 3.2; AEC Qualified: N; AEC Category: Q200
Logo1 = CMP-0074769-1
Logo2 = CMP-0074847-1: FCC_disclaimer; Library Reference: Logo
R14 R18 R24 = CMP-0081856-1: as R3 on sheet PMP22648_Bus + LDO + LS
R15 R20 R26 R32 = CMP-0025958-3: as R9 on sheet PMP22648_Bus + LDO + LS
R16 R19 R25 R31 = CMP-0026703-1: as R5 on sheet PMP22648_Bus + LDO + LS
R17 R21 R27 R33 = CMP-0026753-1: as R2 on sheet PMP22648_Bus + LDO + LS
R22 = CMP-0026182-2: RES, 232 k, 1%, 0.063 W, AEC-Q200 Grade 0, 0402; Manufacturer: Vishay-Dale; Power_W: 63mW; TempCo: 100 ppm/C; Value: 232k; EIA_Code: E96; SizeX_mm: 1; SizeY_mm: 0.5; SizeZ_mm: 0.6; Value2: 0.063W; AEC Qualified: Y; VDC_V: 50V; AEC Category: Q200; AEC Grade: 0
R23 R29 R35 = CMP-0026705-1: RES, 51.0 k, 1%, 0.1 W, AEC-Q200 Grade 0, 0402; Manufacturer: Panasonic; Power_W: 100mW; TempCo: 100 ppm/C; Value_Code: 51k0; U/M: EA; Value: 51.0k; Res_ohm: 51k; SizeX_mm: 1; SizeY_mm: 0.5; SizeZ_mm: 0.6; Value2: 0.1W; AEC Qualified: Y; VDC_V: 50V; AEC Grade: 0; AEC Category: Q200
R28 = CMP-0026498-2: RES, 64.9 k, 1%, 0.063 W, AEC-Q200 Grade 0, 0402; Manufacturer: Vishay-Dale; Power_W: 63mW; TempCo: 100 ppm/C; Value_Code: 64k9; Value: 64.9k; EIA_Code: E96; SizeX_mm: 1; SizeY_mm: 0.5; SizeZ_mm: 0.6; Value2: 0.063W; AEC Qualified: Y; VDC_V: 50V; AEC Category: Q200; AEC Grade: 0
R30 = CMP-0081857-1: RES, 0, 0%,  W, AEC-Q200 Grade 0, 0805; Manufacturer: Rohm; SizeAreaWB_mm2: 6.75; SizeArea_mm2: 2.5; AEC Qualified: Y; AEC Category: Q200; Value: 0; SizeZ_mm: 1.45; SizeY_mm: 1.25; SizeX_mm: 2
R34 = CMP-0026702-1: RES, 49.9 k, 1%, 0.1 W, AEC-Q200 Grade 0, 0402; Manufacturer: Panasonic; Power_W: 100mW; TempCo: 100 ppm/C; Value_Code: 49k9; U/M: EA; Value: 49.9k; EIA_Code: E96; SizeX_mm: 1; SizeY_mm: 0.5; SizeZ_mm: 0.6; Value2: 0.1W; AEC Qualified: Y; VDC_V: 50V; AEC Grade: 0; AEC Category: Q200
TP4 TP6 TP9 TP12 = CMP-0055147-1: as TP2 on sheet PMP22648_Bus + LDO + LS
TP5 TP7 TP10 TP13 = CMP-0055151-1: as TP1 on sheet PMP22648_Bus + LDO + LS
TP8 TP11 TP14 TP18 = CMP-0055148-1: as GND on sheet PMP22648_Bus + LDO + LS
U4 = CMP-0088309-1: 2.7-V to 6-V Adjustable-Frequency Step-Down Converter in SOT583 Package; Manufacturer: Texas Instruments; Number Of Outputs: 1; Switching Topology: Buck; AEC Qualified: Yes; TaMin_C: -40°C; Min Supply Voltage: 2.7V; SizeZ_mm: 0.6mm; Output Type: Fixed; Standoff Height: 0mm; Max Supply Voltage: 6V; Output Voltage: 1.8V; Max Duty Cycle: 100%; Switching Frequency: 1.8-3.5MHz; TJmax_C: +150°C; TaMax_C: +125°C; Nominal Supply Current: 15uA; AEC Grade: Grade 1
U5 U6 = CMP-0088310-1: 2.7-V to 6-V Adjustable-Frequency Step-Down Converter in SOT583 Package; Manufacturer: Texas Instruments; TJmax_C: +150°C; Number Of Outputs: 1; AEC Grade: Grade 1; TaMin_C: -40°C; Min Supply Voltage: 2.7V; TaMax_C: +125°C; Output Type: AdjustableProgrammable; Max Supply Voltage: 6V; Nominal Supply Current: 15uA; Switching Frequency: 1.8-3.5MHz; Max Duty Cycle: 100%; Output Voltage: 0.6-5.5V; AEC Qualified: Yes; Switching Topology: Buck; SizeZ_mm: 0.6mm; Standoff Height: 0mm
U7 = CMP-0088303-1: 2.7-V to 6-V Adjustable-Frequency Step-Down Converter in SOT583 Package; Manufacturer: Texas Instruments; TaMin_C: -40°C; Standoff Height: 0mm; Switching Topology: Buck; Nominal Supply Current: 15uA; Min Supply Voltage: 2.7V; TaMax_C: +125°C; Switching Frequency: 1.8-3.5MHz; Max Supply Voltage: 6V; SizeZ_mm: 0.6mm; Number Of Outputs: 1; Max Duty Cycle: 100%; AEC Qualified: Yes; AEC Grade: Grade 1; Output Voltage: 0.5-5.5V; Output Type: AdjustableProgrammable

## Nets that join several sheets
5V_LS: PMP22648_Bus + LDO + LS (C18.1 TP15.1 U3.7 U3.8), PMP22648_PoL DCDC (8 pins)
GND: PMP22648_Bus + LDO + LS (36 pins), PMP22648_PoL DCDC (40 pins)

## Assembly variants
001: not fitted C1 J15 R1 R36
